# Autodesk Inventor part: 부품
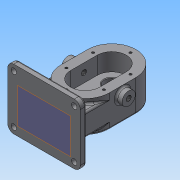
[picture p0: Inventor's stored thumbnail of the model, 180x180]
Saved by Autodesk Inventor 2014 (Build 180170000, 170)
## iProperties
Created: 2020-09
Part Number: 부품
Material: 일반
Document SubType Name: Modeling
Designer: NET
Density: 1 g/cm^3
Appearance: 기본값
Author: NET
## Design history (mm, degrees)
sketch "스케치1"
  geometry: L1 (0, 22)-(0, -22); L2 (-40, 22)-(-40, -22); L3 (40, -22)-(40, 22); A1 r 40 centre (0, 22) between (40, 22) and (-40, 22); A2 r 40 centre (0, -22) between (-40, -22) and (40, -22); 3 further points
  constraints: 8 end point, 4 point on circle, 4 tangent, 2 centre point, 2 midpoint, 1 coincident, 1 horizontal alignment, 1 parallel, 1 vertical
  dimensions: "d4" = 44 distance of L3.start L3.end; "d5" = 40 radius of A1
extrude "돌출1" new body sketch "스케치1" distance "d6" = 53; taper "d7" = 0 deg
sketch "스케치2"
  geometry: L1 (-40, 22)-(-40, -22) reference; L2 (0, 22)-(0, -22); L3 (-24, 22)-(-24, -22); L4 (24, -22)-(24, 22); A1 r 24 centre (0, 22) between (24, 22) and (-24, 22); A2 r 24 centre (0, -22) between (-24, -22) and (24, -22); 2 further points
  constraints: 8 end point, 4 point on circle, 4 tangent, 2 centre point, 2 coincident, 2 parallel, 1 midpoint
  dimensions: "d8" = 24 radius of A1; "d9" = 44 distance of L4.start L4.end
extrude "돌출2" cut sketch "스케치2" distance "d10" = 29; taper "d11" = 0 deg
node "작업 평면1"
sketch "스케치3"
  geometry: C1 r 12.5 at (0, 22); C2 r 12.5 at (0, -22); A1 r 24 centre (0, -22) between (-24, -22) and (24, -22) reference; A2 r 24 centre (0, 22) between (24, 22) and (-24, 22) reference; 1 further point
  constraints: 2 centre point, 2 coincident
  dimensions: "d13" = 25 diameter of C1; "d14" = 25 diameter of C2
extrude "돌출3" cut sketch "스케치3" distance "d15" = 15; taper "d16" = 0 deg
sketch "스케치4"
  geometry: C1 r 12.5 at (0, 0) reference; C2 r 8.5 at (0, 0); 1 further point
  constraints: 1 centre point, 1 coincident
  dimensions: "d17" = 17 diameter of C2
extrude "돌출4" cut sketch "스케치4" stored distance "d18" = 15; taper "d19" = 0 deg
sketch "스케치5"
  geometry: C1 r 8.5 at (0, 22) reference; C2 r 19 at (0, 22); A1 r 40 centre (0, 22) between (40, 22) and (-40, 22) reference; 1 further point
  constraints: 1 centre point, 1 coincident
  dimensions: "d20" = 38 diameter of C2
extrude "돌출5" join sketch "스케치5" distance "d21" = 17; taper "d22" = 0 deg
sketch "스케치6"
  geometry: C1 r 8.5 at (0, 0) reference; C2 r 19 at (0, 0) reference; C3 r 14 at (0, 0); 1 further point
  constraints: 1 centre point, 1 coincident
  dimensions: "d23" = 28 diameter of C3
extrude "돌출6" cut sketch "스케치6" distance "d24" = 7.3; taper "d25" = 0 deg
sketch "스케치7"
  geometry: L1 (-19, -17)-(19, -17) reference; L2 (-60, 83)-(60, 83); L3 (60, 83)-(60, -17); L4 (60, -17)-(-60, -17); L5 (-60, -17)-(-60, 83); 2 further points
  constraints: 8 end point, 3 parallel, 2 midpoint, 1 perpendicular
  dimensions: "d26" = 100 distance of L2.end L3.end; "d27" = 120 distance of L3.end L4.end
extrude "돌출7" join sketch "스케치7" distance "d28" = 10; taper "d29" = 0 deg
sketch "스케치8"
  geometry: L1 (60, 17)-(-60, 17) reference; L2 (-40, -45)-(40, -45); L3 (40, -45)-(40, -8); L4 (40, -8)-(-40, -8); L5 (-40, -45)-(-40, -8); 2 further points
  constraints: 8 end point, 2 vertical, 1 horizontal, 1 midpoint, 1 perpendicular, 1 vertical alignment
  dimensions: "d30" = 80 distance of L2.start L2.end; "d31" = 37 distance of L2.end L3.end; "d32" = 25 distance between parallel lines of L1 L4
extrude "돌출8" join sketch "스케치8" stored distance "d33" = 10; taper "d34" = 0 deg
node "작업 평면2"
sketch "스케치9"
  geometry: L1 (-90, 83)-(-90, -17) reference; L2 (-22, 53)-(22, 53) reference; C1 r 11 at (0, 39); 2 further points
  constraints: 1 centre point, 1 midpoint, 1 vertical alignment
  dimensions: "d36" = 22 diameter of C1; "d72" = 14 distance from line of L2 C1.centre
extrude "돌출9" join sketch "스케치9" stored distance "d37" = 10; taper "d38" = 0 deg
sketch "스케치10"
  geometry: C1 r 11 at (0, 0) reference; 2 further points
  constraints: 1 coincident
hole "구멍1" sketch "스케치10" at (0, 0) diameter "d39" = 8.376; stored, may be unused: countersink angle "d43" = 90 deg, drill point angle "d45" = 118 deg; dims "d40" = 6, "d41" = 4, "d42" = 2, "d44" = 8
sketch "스케치11"
  geometry: A1 r 24 centre (0, -22) between (-24, -22) and (24, -22) reference; A2 r 24 centre (0, 22) between (24, 22) and (-24, 22) reference; 7 further points
  constraints: 4 horizontal alignment, 4 vertical alignment
  dimensions: "d46" = 31 distance of A1.centre point (-31, -22); "d47" = 31 distance of point (31, 22) A2.centre; "d48" = 31 distance of point (0, 53) A2.centre; "d49" = 31 distance of point (0, -53) A1.centre
hole "구멍2" sketch "스케치11" at (0, 53), (31, 22), (-31, 22), (-31, -22), (31, -22), (0, -53) diameter "d50" = 4.134; stored, may be unused: countersink angle "d54" = 90 deg, drill point angle "d56" = 118 deg; dims "d51" = 10, "d52" = 4, "d53" = 2, "d55" = 12
chamfer "모따기1" distance "d57" = 0.7; stored, may be unused: second distance "d58" = 2, angle "d59" = 30 deg
chamfer "모따기2" distance "d60" = 1; stored, may be unused: second distance "d61" = 2, angle "d62" = 30 deg
sketch "스케치12"
  geometry: L1 (-60, -83)-(60, -83) reference; L2 (60, -83)-(60, 17) reference; L3 (60, 17)-(-60, 17) reference; L4 (-60, 17)-(-60, -83) reference; C1 r 4.5 at (-50, 7); C2 r 4.5 at (50, 7); C3 r 4.5 at (50, -73); C4 r 4.5 at (-50, -73); 1 further point
  constraints: 4 centre point, 3 equal radius, 2 horizontal alignment, 2 vertical alignment
  dimensions: "d63" = 9 diameter of C1; "d64" = 10 distance from line of L3 C1.centre; "d65" = 10 distance from line of L4 C1.centre; "d66" = 10 distance from line of L2 C2.centre; "d67" = 10 distance from line of L1 C4.centre
extrude "돌출10" cut sketch "스케치12" distance "d68" = 10; taper "d69" = 0 deg
fillet "모깎기1" dims "d70" = 3
fillet "모깎기2" dims "d71" = 3
fillet "모깎기3" dims "d73" = 10
fillet "모깎기4" dims "d74" = 3
fillet "모깎기5" dims "d75" = 3
sketch "스케치13"
  geometry: L1 (-50, -83)-(50, -83) reference; L2 (-60, 7)-(-60, -73) reference; 2 further points
  constraints: 1 other
  dimensions: "d76" = 12 distance from line of L1 point (0, -71); "d77" = 60 distance from line of point (0, -71) L2
feature "엠보싱1" sketch "스케치13" dims "d4" = 44, "d5" = 40, "d78" = 0.5, "d79" = 0
node "솔리드1"
mirror "대칭1"
